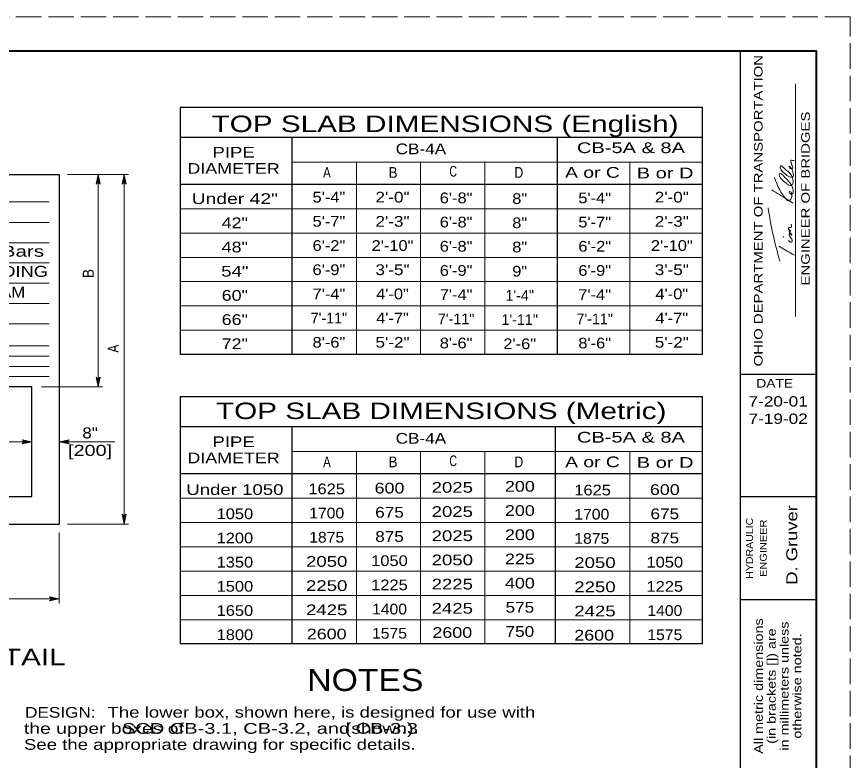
# Model space of a CAD drawing. Extents: x 1073.4 to 1107.4, y 719.4 to 741.4.
# Drawn here: x 1095.2 to 1107.36, y 730.51 to 741.35 of the extents above; entities that cross this region are included whole.
import ezdxf
from ezdxf.enums import TextEntityAlignment as Align

# ---------------------------------------------------------------- set-up
doc = ezdxf.new("R2010")
doc.units = 0
doc.header["$LTSCALE"] = 0.062
doc.linetypes.add('LONG_DASHED', pattern=[7.5, 6, -1.5])
doc.layers.add('1', color=7, linetype='Continuous', lineweight=13)

msp = doc.modelspace()

# ---------------------------------------------------------------- linework, layer by layer
at = {"layer": '1', "lineweight": 25}
for p, q in [((1075.36142, 740.85408), (1106.86142, 740.85408)), ((1105.76142, 719.85408), (1105.76142, 740.85408)), ((1106.86142, 740.85408), (1106.86142, 719.85408)), ((1105.20608, 740.03175), (1097.58467, 740.03175)), ((1097.58467, 740.03175), (1097.58467, 736.4295)), ((1105.20608, 736.4295), (1105.20608, 740.03175)), ((1105.20608, 739.5945), (1097.58467, 739.5945)), ((1099.21792, 736.4295), (1099.21792, 739.5945)), ((1103.09108, 736.4295), (1103.09108, 739.5945)), ((1105.20608, 738.9075), (1097.58467, 738.9075)), ((1105.20608, 736.4295), (1097.58467, 736.4295)), ((1106.86142, 736.13825), (1105.76142, 736.13825)), ((1097.58467, 735.812), (1097.58467, 732.20967)), ((1105.20608, 735.812), (1097.58467, 735.812)), ((1105.20608, 732.20967), (1105.20608, 735.812)), ((1105.20608, 735.37475), (1097.58467, 735.37475)), ((1099.21792, 732.20967), (1099.21792, 735.37475)), ((1103.06158, 732.20967), (1103.06158, 735.37475)), ((1105.20608, 734.68767), (1097.58467, 734.68767)), ((1106.86142, 734.35408), (1105.76142, 734.35408)), ((1091.99858, 733.95817), (1095.82183, 733.95817)), ((1106.86142, 732.85408), (1105.76142, 732.85408)), ((1105.20608, 732.20967), (1097.58467, 732.20967))]:
    msp.add_line(p, q, dxfattribs=at)
at = {"layer": '1'}
for p, q in [((1106.56017, 736.98508), (1106.56017, 740.37517)), ((1105.20608, 739.23533), (1099.21792, 739.23533)), ((1100.15492, 736.4295), (1100.15492, 739.23533)), ((1101.092, 736.4295), (1101.092, 739.23533)), ((1102.02908, 736.4295), (1102.02908, 739.23533)), ((1104.14442, 736.4295), (1104.14442, 739.23533)), ((1096.82942, 739.05525), (1095.94175, 739.05525)), ((1096.36758, 738.92558), (1096.38742, 739.05525)), ((1096.37583, 738.9305), (1096.38742, 739.05525)), ((1096.38742, 739.05525), (1096.3875, 737.45208)), ((1096.38742, 738.93275), (1096.38742, 739.05525)), ((1096.3965, 738.9315), (1096.38742, 739.05525)), ((1096.40533, 738.92708), (1096.38742, 739.05525)), ((1096.74658, 738.92558), (1096.7665, 739.05525)), ((1096.75492, 738.9305), (1096.7665, 739.05525)), ((1096.7665, 738.93275), (1096.7665, 739.05525)), ((1096.7755, 738.9315), (1096.7665, 739.05525)), ((1096.78442, 738.92708), (1096.7665, 739.05525)), ((1092.1485, 738.65533), (1095.67183, 738.65533)), ((1105.20608, 738.5535), (1097.58467, 738.5535)), ((1092.1485, 738.3555), (1095.67183, 738.3555)), ((1105.20608, 738.1995), (1097.58467, 738.1995)), ((1106.39267, 738.136), (1106.3825, 738.15525)), ((1092.1485, 738.05958), (1095.67183, 738.05958)), ((1092.1485, 737.76375), (1095.67183, 737.76375)), ((1105.20608, 737.8455), (1097.58467, 737.8455)), ((1092.1485, 737.46783), (1095.67183, 737.46783)), ((1096.38725, 735.95708), (1096.3875, 737.45208)), ((1096.38725, 735.95708), (1096.3875, 737.45208)), ((1105.20608, 737.4915), (1097.58467, 737.4915)), ((1092.1485, 737.17192), (1095.67183, 737.17192)), ((1105.20608, 737.1375), (1097.58467, 737.1375)), ((1092.1485, 736.87608), (1095.67183, 736.87608)), ((1105.20608, 736.7835), (1097.58467, 736.7835)), ((1092.1485, 736.5565), (1095.67183, 736.5565)), ((1092.1485, 736.40667), (1095.67183, 736.40667)), ((1096.76617, 733.95817), (1096.76617, 736.36992)), ((1092.1485, 736.25675), (1095.67183, 736.25675)), ((1092.1485, 736.10683), (1095.67183, 736.10683)), ((1096.36933, 736.08525), (1096.38725, 735.95708)), ((1096.37817, 736.08092), (1096.38725, 735.95708)), ((1096.40708, 736.08683), (1096.38725, 735.95708)), ((1096.39883, 736.08183), (1096.38725, 735.95708)), ((1096.38725, 736.07958), (1096.38725, 735.95708)), ((1096.45017, 735.957), (1095.5635, 735.957)), ((1095.08658, 735.1575), (1095.422, 735.1575)), ((1095.29225, 735.13767), (1095.422, 735.1575)), ((1095.29383, 735.17542), (1095.422, 735.1575)), ((1095.29717, 735.146), (1095.422, 735.1575)), ((1095.29817, 735.1665), (1095.422, 735.1575)), ((1095.2995, 735.1575), (1095.422, 735.1575)), ((1095.95, 735.17542), (1095.82183, 735.1575)), ((1095.94567, 735.1665), (1095.82183, 735.1575)), ((1095.82183, 735.1575), (1096.62917, 735.1575)), ((1095.94433, 735.1575), (1095.82183, 735.1575)), ((1095.94658, 735.146), (1095.82183, 735.1575)), ((1095.9515, 735.13767), (1095.82183, 735.1575)), ((1105.20608, 735.01558), (1099.21792, 735.01558)), ((1100.15492, 732.20967), (1100.15492, 735.01558)), ((1101.092, 732.20967), (1101.092, 735.01558)), ((1102.02908, 732.20967), (1102.02908, 735.01558)), ((1104.14442, 732.20967), (1104.14442, 735.01558)), ((1105.20608, 734.33367), (1097.58467, 734.33367)), ((1096.74817, 734.08642), (1096.76617, 733.95817)), ((1096.75708, 734.08208), (1096.76617, 733.95817)), ((1096.78592, 734.08792), (1096.76617, 733.95817)), ((1096.77767, 734.083), (1096.76617, 733.95817)), ((1096.7665, 734.08075), (1096.7665, 733.95817)), ((1105.20608, 733.97967), (1097.58467, 733.97967)), ((1096.82942, 733.95817), (1095.94175, 733.95817)), ((1095.82183, 732.80033), (1095.82183, 733.83283)), ((1105.20608, 733.62567), (1097.58467, 733.62567)), ((1105.20608, 733.27167), (1097.58467, 733.27167)), ((1095.69358, 732.88492), (1095.82183, 732.867)), ((1095.698, 732.87608), (1095.82183, 732.867)), ((1105.20608, 732.91767), (1097.58467, 732.91767)), ((1091.99858, 732.867), (1095.82183, 732.867)), ((1095.69217, 732.84717), (1095.82183, 732.867)), ((1095.697, 732.8555), (1095.82183, 732.867)), ((1095.69925, 732.867), (1095.82183, 732.867)), ((1105.20608, 732.56367), (1097.58467, 732.56367))]:
    msp.add_line(p, q, dxfattribs=at)
at = {"layer": '1', "linetype": 'LONG_DASHED'}
msp.add_lwpolyline([(1073.36142, 719.35408), (1107.36142, 719.35408), (1107.36142, 741.35408), (1073.36142, 741.35408)], close=True, dxfattribs=at)
at = {"layer": '1', "lineweight": 40}
msp.add_lwpolyline([(1075.36142, 740.85408), (1106.86142, 740.85408), (1106.86142, 719.85408), (1075.36142, 719.85408)], close=True, dxfattribs=at)
msp.add_lwpolyline([(1075.36142, 740.85408), (1106.86142, 740.85408), (1106.86142, 719.85408), (1075.36142, 719.85408)], close=True, dxfattribs=at)
at = {"layer": '1', "lineweight": 25}
msp.add_lwpolyline([(1091.99858, 739.05525), (1095.82183, 739.05525), (1095.82183, 733.95817)], dxfattribs=at)
at = {"layer": '1'}
for points in [[(1096.35908, 738.91367), (1096.38742, 739.05525), (1096.41575, 738.91367)], [(1096.73817, 738.91367), (1096.7665, 739.05525), (1096.79483, 738.91367)], [(1096.7665, 733.95817), (1096.7665, 736.36992), (1096.7665, 739.05525)], [(1096.41558, 736.09867), (1096.38725, 735.95708), (1096.35892, 736.09867)], [(1095.28042, 735.12917), (1095.422, 735.1575), (1095.28042, 735.18583)], [(1095.96342, 735.12917), (1095.82183, 735.1575), (1095.96342, 735.18583)], [(1096.7945, 734.09983), (1096.76617, 733.95817), (1096.73783, 734.09983)], [(1095.68017, 732.83867), (1095.82183, 732.867), (1095.68017, 732.89525)]]:
    msp.add_lwpolyline(points, dxfattribs=at)
at = {"layer": '1', "lineweight": 25}
msp.add_lwpolyline([(1095.422, 734.35792), (1095.422, 735.957), (1093.82275, 735.957), (1093.82275, 734.35792)], close=True, dxfattribs=at)
at = {"layer": '1'}
for centre, start, end in [((1096.38743, 738.90226), 22.08782, 157.91395), ((1096.76649, 738.90226), 22.08782, 157.91395), ((1096.38723, 736.11011), 202.08782, 337.91395), ((1095.26894, 735.15752), 292.08605, 67.91218), ((1095.97482, 735.15752), 112.08782, 247.91395), ((1096.76609, 734.11126), 202.08782, 337.91395), ((1095.66879, 732.867), 292.08605, 67.91218)]:
    msp.add_arc(centre, 0.03056, start, end, dxfattribs=at)
for points in [[(1106.25325, 739.01108), (1106.43642, 738.68275), (1106.45158, 738.67217), (1106.46175, 738.67217), (1106.49367, 738.69583), (1106.50875, 738.73), (1106.50375, 738.78125), (1106.48683, 738.80308), (1106.47333, 738.80308), (1106.47158, 738.79008), (1106.48175, 738.77492), (1106.49525, 738.7665), (1106.51033, 738.7665), (1106.5255, 738.78808), (1106.52892, 738.80742), (1106.51867, 738.86275), (1106.43642, 738.98317), (1106.39092, 739.02783), (1106.354, 739.06242), (1106.32883, 739.06458), (1106.33058, 739.026), (1106.35575, 738.98725), (1106.423, 738.92492), (1106.46508, 738.8995), (1106.49875, 738.895), (1106.52208, 738.921), (1106.52892, 738.95517), (1106.52383, 738.98092), (1106.49367, 739.05408), (1106.46342, 739.08608), (1106.40283, 739.1395), (1106.37417, 739.16533), (1106.34067, 739.18058), (1106.33725, 739.15258), (1106.34733, 739.12675), (1106.4045, 739.06683), (1106.47517, 739.01958), (1106.52717, 739.02192), (1106.5255, 739.07958), (1106.51367, 739.1225), (1106.50033, 739.14825), (1106.49017, 739.159), (1106.46675, 739.174), (1106.4685, 739.15692), (1106.50375, 739.13542), (1106.51867, 739.14617), (1106.50558, 739.19983), (1106.497, 739.22775), (1106.49367, 739.24042), (1106.49367, 739.25325), (1106.49367, 739.26192), (1106.51867, 739.25975), (1106.54408, 739.25975)], [(1106.21442, 738.82883), (1106.43817, 738.69133), (1106.52383, 738.63567)], [(1106.33067, 737.79183), (1106.232, 738.18708), (1106.16075, 738.56942)], [(1106.46175, 738.09075), (1106.47, 738.08008), (1106.50717, 738.06717), (1106.51192, 738.09958), (1106.48683, 738.136), (1106.47158, 738.17225), (1106.47158, 738.1915), (1106.48683, 738.18525), (1106.497, 738.17442), (1106.50717, 738.17008), (1106.4835, 738.20225), (1106.47158, 738.21725), (1106.4685, 738.23458), (1106.49192, 738.228), (1106.4835, 738.23667), (1106.45833, 738.2645), (1106.4685, 738.27967), (1106.48525, 738.28167), (1106.49367, 738.27967), (1106.50375, 738.301), (1106.497, 738.32892)], [(1106.54583, 737.87625), (1106.34067, 737.99625), (1106.32508, 738.00667)]]:
    msp.add_spline(points, degree=3, dxfattribs=at)

# ---------------------------------------------------------------- texts
for s, height, width, p in [('OHIO DEPARTMENT OF TRANSPORTATION', 0.125, 1.3, (1106.08133, 738.52633)), ('ENGINEER OF BRIDGES', 0.125, 1.3, (1106.76967, 738.70312)), ('D. Gruver', 0.16, 1.25, (1106.58717, 733.65292)), ('HYDRAULIC', 0.1, 1.15, (1105.9405, 733.60517)), ('ENGINEER', 0.1, 1.2, (1106.14142, 733.60521)), ('All metric dimensions', 0.125, 1.25, (1106.08525, 731.59617)), ('in millimeters unless', 0.125, 1.25, (1106.46025, 731.59621)), ('(in brackets []) are', 0.125, 1.25, (1106.27275, 731.59617)), ('otherwise noted.', 0.125, 1.25, (1106.64775, 731.59617))]:
    msp.add_text(s, height=height, rotation=90, dxfattribs=dict(at, width=width)).set_placement(p, align=Align.CENTER)
for s, height, width, p in [('TOP SLAB DIMENSIONS (English)', 0.24, 1.35, (1098.04225, 739.67242)), ('CB-4A', 0.156, 1.2, (1100.72808, 739.34917)), ('CB-5A & 8A', 0.156, 1.4, (1103.37392, 739.36558)), ('A', 0.156, 0.8, (1099.67, 739.00575)), ('B', 0.156, 0.95, (1100.6235, 739.00575)), ('C', 0.156, 0.75, (1101.51133, 739.02217)), ('D', 0.156, 0.85, (1102.46175, 739.00575)), ('A or C', 0.156, 1.35, (1103.20017, 739.00575)), ('B or D', 0.156, 1.4, (1104.24558, 738.99758)), ('#6 [#19M] Bars', 0.16, 1.4, (1093.5675, 737.85483)), ('See BENDING', 0.16, 1.25, (1093.88842, 737.56125)), ('DIAGRAM', 0.16, 1.15, (1094.17675, 737.259)), ('TOP SLAB DIMENSIONS (Metric)', 0.24, 1.35, (1098.10692, 735.48825)), ('CB-4A', 0.156, 1.2, (1100.72808, 735.12942)), ('CB-5A & 8A', 0.156, 1.4, (1103.37392, 735.14583)), ('C', 0.156, 0.75, (1101.51133, 734.80242)), ('A or C', 0.156, 1.35, (1103.20017, 734.78592)), ('A', 0.156, 0.8, (1099.67, 734.78592)), ('B', 0.156, 0.95, (1100.6235, 734.78592)), ('D', 0.156, 0.85, (1102.46175, 734.78592)), ('B or D', 0.156, 1.4, (1104.24558, 734.77783)), ('1625', 0.156, 1.15, (1103.3345, 734.37542)), ('1700', 0.156, 1.1, (1103.3345, 734.02275)), ('1875', 0.156, 1.1, (1103.3345, 733.67008)), ('2050', 0.156, 1.3, (1103.3345, 733.31742)), ('2250', 0.156, 1.3, (1103.3345, 732.96475)), ('2425', 0.156, 1.3, (1103.3345, 732.61208)), ('2600', 0.156, 1.25, (1103.3345, 732.25942)), ('TOP SLAB DETAIL', 0.24, 1.35, (1092.15842, 731.89892)), ('NOTES', 0.32, 1.15, (1099.4385, 731.52458)), ('The lower box, shown here, is designed for use with', 0.156, 1.3, (1096.52467, 731.13675)), ('DESIGN:', 0.156, 1.2, (1095.32158, 731.1345)), ('the upper boxes of                              (shown).', 0.156, 1.35, (1095.30583, 730.90067)), ('                  SCD CB-3.1, CB-3.2, and CB-3.3 ', 0.156, 1.4, (1095.27567, 730.90075)), ('See the appropriate drawing for specific details.', 0.156, 1.3, (1095.30583, 730.66667))]:
    msp.add_text(s, height=height, dxfattribs=dict(at, width=width)).set_placement(p)
for s, height, width, p in [('PIPE', 0.156, 1.3, (1098.36392, 739.29933)), ('DIAMETER', 0.156, 1.25, (1098.36383, 739.06333)), ('Under 42"', 0.156, 1.35, (1098.38188, 738.62358)), ('5\'-4"', 0.156, 1.15, (1099.75471, 738.64533)), ('2\'-0"', 0.156, 1.2, (1100.68254, 738.64533)), ('6\'-8"', 0.156, 1.15, (1101.6105, 738.6345)), ('8"', 0.156, 1.15, (1102.53833, 738.62358)), ('5\'-4"', 0.156, 1.15, (1103.63204, 738.6345)), ('2\'-0"', 0.156, 1.2, (1104.75704, 738.64533)), ('42"', 0.156, 1.25, (1098.38192, 738.27092)), ('5\'-7"', 0.156, 1.15, (1099.75471, 738.29267)), ('2\'-3"', 0.156, 1.2, (1100.68262, 738.29267)), ('6\'-8"', 0.156, 1.15, (1101.6105, 738.28183)), ('8"', 0.156, 1.15, (1102.53833, 738.27092)), ('5\'-7"', 0.156, 1.15, (1103.63204, 738.28183)), ('2\'-3"', 0.156, 1.2, (1104.75712, 738.29267)), ('48"', 0.156, 1.25, (1098.38196, 737.91825)), ('6\'-2"', 0.156, 1.15, (1099.75475, 737.94)), ('2\'-10"', 0.156, 1.15, (1100.68258, 737.94)), ('6\'-8"', 0.156, 1.15, (1101.6105, 737.92917)), ('8"', 0.156, 1.15, (1102.53833, 737.91825)), ('6\'-2"', 0.156, 1.15, (1103.63208, 737.92917)), ('2\'-10"', 0.156, 1.15, (1104.75708, 737.94)), ('6\'-9"', 0.156, 1.15, (1099.75471, 737.58733)), ('3\'-5"', 0.156, 1.2, (1100.68254, 737.58733)), ('3\'-5"', 0.156, 1.2, (1104.75704, 737.58733)), ('54"', 0.156, 1.3, (1098.38192, 737.56558)), ('6\'-9"', 0.156, 1.15, (1101.61046, 737.5765)), ('9"', 0.156, 1.15, (1102.53833, 737.56558)), ('6\'-9"', 0.156, 1.15, (1103.63204, 737.5765)), ('7\'-4"', 0.156, 1.15, (1099.75471, 737.23467)), ('4\'-0"', 0.156, 1.15, (1100.68258, 737.23467)), ('7\'-4"', 0.156, 1.15, (1101.61046, 737.22383)), ('7\'-4"', 0.156, 1.15, (1103.63204, 737.22383)), ('4\'-0"', 0.156, 1.15, (1104.75708, 737.23467)), ('60"', 0.156, 1.25, (1098.38192, 737.21292)), ('66"', 0.156, 1.25, (1098.38192, 736.86025)), ('4\'-7"', 0.156, 1.15, (1100.68254, 736.882)), ('4\'-7"', 0.156, 1.15, (1104.75704, 736.882)), ('72"', 0.156, 1.25, (1098.38192, 736.50758)), ('8\'-6"', 0.156, 1.15, (1099.75475, 736.52933)), ('5\'-2"', 0.156, 1.2, (1100.68262, 736.52933)), ('8\'-6"', 0.156, 1.15, (1101.6105, 736.5185)), ('2\'-6"', 0.156, 1.15, (1102.53833, 736.50758)), ('8\'-6"', 0.156, 1.15, (1103.63208, 736.5185)), ('5\'-2"', 0.156, 1.2, (1104.75712, 736.52933)), ('DATE', 0.125, 1.2, (1106.25813, 735.94683)), ('7-20-01', 0.15, 1.25, (1106.30846, 735.67133)), ('7-19-02', 0.15, 1.25, (1106.30846, 735.41825)), ('8"', 0.16, 1.15, (1096.27046, 735.20617)), ('PIPE', 0.156, 1.3, (1098.36392, 735.07958)), ('[200]', 0.16, 1.35, (1096.27054, 734.95175)), ('DIAMETER', 0.156, 1.25, (1098.36383, 734.84358)), ('200', 0.156, 1.25, (1102.54062, 734.42958)), ('Under 1050', 0.156, 1.3, (1098.383, 734.38242)), ('1625', 0.156, 1.15, (1099.72229, 734.39292)), ('600', 0.156, 1.25, (1100.6385, 734.40383)), ('2025', 0.156, 1.3, (1101.55479, 734.41467)), ('600', 0.156, 1.25, (1104.655, 734.38208)), ('2025', 0.156, 1.3, (1101.55479, 734.062)), ('200', 0.156, 1.25, (1102.54062, 734.07692)), ('1050', 0.156, 1.15, (1098.38304, 734.02975)), ('1700', 0.156, 1.1, (1099.72229, 734.04025)), ('675', 0.156, 1.2, (1100.63846, 734.05117)), ('675', 0.156, 1.2, (1104.65496, 734.02942)), ('875', 0.156, 1.2, (1100.63846, 733.6985)), ('2025', 0.156, 1.3, (1101.55479, 733.70933)), ('200', 0.156, 1.25, (1102.54062, 733.72425)), ('1200', 0.156, 1.15, (1098.383, 733.67708)), ('1875', 0.156, 1.1, (1099.72221, 733.68758)), ('875', 0.156, 1.2, (1104.65496, 733.67675)), ('2050', 0.156, 1.3, (1099.72229, 733.33492)), ('1050', 0.156, 1.15, (1100.63854, 733.34583)), ('2050', 0.156, 1.3, (1101.55488, 733.35667)), ('225', 0.156, 1.25, (1102.54062, 733.37158)), ('1350', 0.156, 1.15, (1098.38296, 733.32442)), ('1050', 0.156, 1.15, (1104.65504, 733.32408)), ('1500', 0.156, 1.15, (1098.38304, 732.97175)), ('2250', 0.156, 1.3, (1099.72229, 732.98225)), ('1225', 0.156, 1.15, (1100.63846, 732.99317)), ('2225', 0.156, 1.3, (1101.55479, 733.004)), ('400', 0.156, 1.25, (1102.54067, 733.01892)), ('1225', 0.156, 1.15, (1104.65496, 732.97142)), ('1650', 0.156, 1.15, (1098.38296, 732.61908)), ('2425', 0.156, 1.3, (1099.72225, 732.62958)), ('1400', 0.156, 1.1, (1100.6385, 732.6405)), ('2425', 0.156, 1.3, (1101.55483, 732.65133)), ('575', 0.156, 1.2, (1102.54067, 732.66625)), ('1400', 0.156, 1.1, (1104.655, 732.61875)), ('1800', 0.156, 1.15, (1098.383, 732.26642)), ('2600', 0.156, 1.25, (1099.72225, 732.27692)), ('1575', 0.156, 1.1, (1100.6385, 732.28783)), ('2600', 0.156, 1.25, (1101.55483, 732.29867)), ('750', 0.156, 1.2, (1102.54062, 732.31358)), ('1575', 0.156, 1.1, (1104.655, 732.26608))]:
    msp.add_text(s, height=height, dxfattribs=dict(at, width=width)).set_placement(p, align=Align.CENTER)
for s, width, p in [('B', 0.95, (1096.32408, 737.54083)), ('A', 0.8, (1096.68842, 736.45742))]:
    msp.add_text(s, height=0.16, rotation=90, dxfattribs=dict(at, width=width)).set_placement(p)
for s, p in [('1\'-4"', (1102.53837, 737.21292)), ('7\'-11"', (1099.75479, 736.882)), ('7\'-11"', (1101.61054, 736.87117)), ('1\'-11"', (1102.53829, 736.86025)), ('7\'-11"', (1103.63212, 736.87117))]:
    msp.add_text(s, height=0.156, dxfattribs=at).set_placement(p, align=Align.CENTER)

doc.saveas('drawing.dxf')
